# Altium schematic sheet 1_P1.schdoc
size 307 x 218 mm; Symbol: Drawing-Symbol_A4; Device: Drawing-Symbol_A4; @Project Name: grandPA2; @Page Count: 1; @Update Date: 2026-07-17; @Create Date: 2026-07-16; @Schematic Name: peripherals; @Page No: 1; @Page Name: P1; Company: EasyEDA.com; Version: v0.2; Page Size: A4; @Create Time: 16:22:37; @Update Time: 20:40:44; Width: 1170; Height: 825; Region Start: 1; X Region Count: 6; Y Region Count: 4; Blade Width: 10; Title Block Position: 3; @Board Name: peripherals
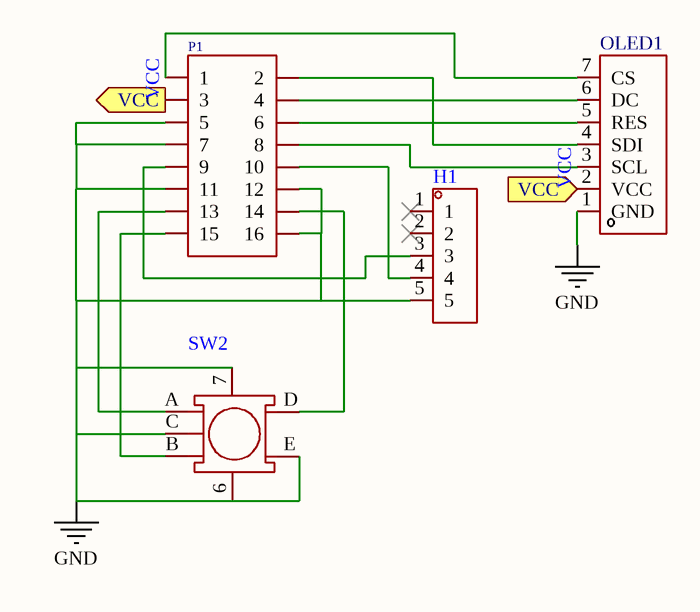
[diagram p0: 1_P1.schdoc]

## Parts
H1  (no value)  [HDR-TH_5P-P2.54-V-M]
OLED1  HS13L02W4S01  [OLED-TH_HS13L02W4S01]  (value not drawn)
P1  2.54-2*8P简牛  [IDC-TH_16P-P2.54_C3406]  (value not drawn)
SW2  (no value)  [SW-TH_EC11XXXXXXXX]

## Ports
VCC (in), VCC (out)

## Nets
GND: H1.5 OLED1.1(GND) P1.5 P1.7 P1.11 P1.12 P1.16 SW2.6 SW2.7 SW2.C SW2.E
VCC: OLED1.2(VCC) P1.3 ; port VCC
NetH1_3: H1.3 P1.9
NetH1_4: H1.4 P1.10
NetOLED1_3: OLED1.3(SCL) P1.8
NetOLED1_4: OLED1.4(SDI) P1.2
NetOLED1_5: OLED1.5(RES) P1.6
NetOLED1_6: OLED1.6(DC) P1.4
NetOLED1_7: OLED1.7(CS) P1.1
NetP1_13: P1.13 SW2.A
NetP1_14: P1.14 SW2.D
NetP1_15: P1.15 SW2.B

Not connected (* = marked no-connect by the designer): H1 1* 2*

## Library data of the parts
H1 = HDR-M_2.54_1x5P: Symbol: MTP125-1105S1; Convert to PCB: yes
OLED1 = HS13L02W4S01: Manufacturer: HS(汉昇); Add into BOM: yes; Controller Type: SH1106 chip; Dot Pixels: 128x64; Type of Drive: Passive (PMOLED); Display Range: 29.42x14.7mm; Display Color: White; Luminance: 150cd/m2
P1 = 2.54-2*8P简牛: Manufacturer: BOOMELE(博穆精密); Symbol: HDR-IDC-2.54-2X8P; Add into BOM: yes; Connector Type: IDC Header; Pitch: 2.54mm; Number of Positions or Pins: 2x8P; Current Rating: 1A; Holder Type: Through Hole; Number of PINs Per Row: 8
SW2 = EC11E15244B2: Symbol: 旋转编码器; Add into BOM: yes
